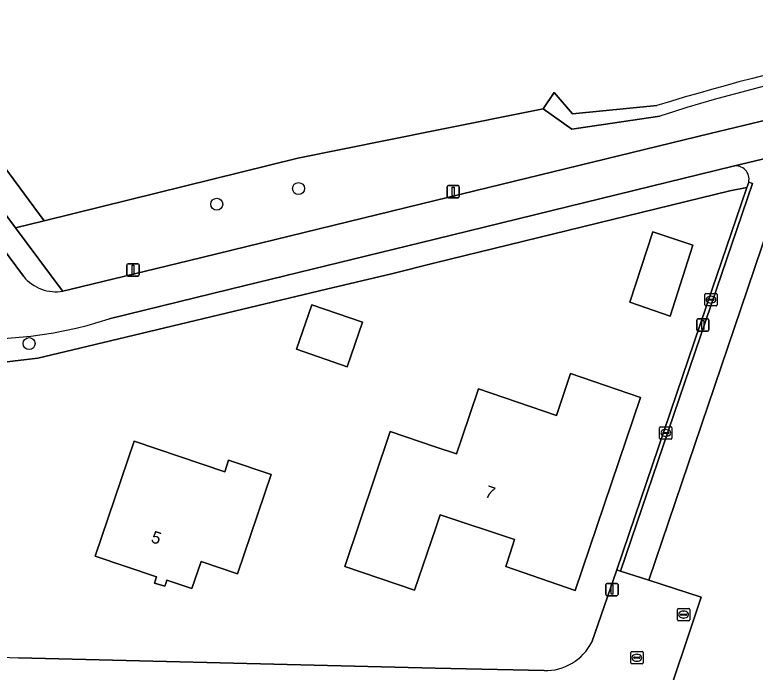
# Model space of a CAD drawing. Extents: x 163426 to 164192, y 380329 to 381641.
# Drawn here: x 163965.7 to 164026.1, y 380968.8 to 381022.4 of the extents above; entities that cross this region are included whole.
import ezdxf

# ---------------------------------------------------------------- set-up
doc = ezdxf.new("R2010")
doc.units = 0
for name, color, linetype in [('IMGEO_Boom', 7, 'Continuous'), ('IMGEO_Brandkraan', 7, 'Continuous'), ('IMGEO_Erf', 7, 'Continuous'), ('IMGEO_Fietspad_open', 7, 'Continuous'), ('IMGEO_Groenvoorziening', 7, 'Continuous'), ('IMGEO_Hek', 7, 'Continuous'), ('IMGEO_Kolk', 7, 'Continuous'), ('IMGEO_Lichtmast', 7, 'Continuous'), ('IMGEO_Pand', 7, 'Continuous'), ('IMGEO_Pand_nummerreeks', 7, 'Continuous'), ('IMGEO_Rijbaan_lokaal_open', 7, 'Continuous'), ('IMGEO_Voetpad_open', 7, 'Continuous'), ('IMGEO_Waterloop', 7, 'Continuous')]:
    doc.layers.add(name, color=color, linetype=linetype)

msp = doc.modelspace()

# ---------------------------------------------------------------- linework, layer by layer
at = {"layer": 'IMGEO_Boom'}
for centre in [(163988.865, 381008.202), (163982.196, 381006.926), (163966.911, 380995.571)]:
    msp.add_circle(centre, 0.489, dxfattribs=at)
at = {"layer": 'IMGEO_Brandkraan'}
for p, q in [((164019.731, 380973.078), (164019.731, 380973.93)), ((164019.806, 380974.004), (164020.658, 380974.004)), ((164020.219, 380973.784), (164020.244, 380973.784)), ((164020.732, 380973.93), (164020.732, 380973.078)), ((164019.99, 380973.498), (164019.99, 380973.51)), ((164020.428, 380973.461), (164020.03, 380973.461)), ((164020.033, 380973.547), (164020.431, 380973.547)), ((164020.242, 380973.224), (164020.217, 380973.224)), ((164020.474, 380973.51), (164020.474, 380973.498)), ((164020.658, 380973.004), (164019.806, 380973.004))]:
    msp.add_line(p, q, dxfattribs=at)
for points in [[(164019.731, 380973.078), (164019.731, 380973.93)], [(164019.806, 380974.004), (164020.658, 380974.004)], [(164020.732, 380973.93), (164020.732, 380973.078)], [(164020.658, 380973.004), (164019.806, 380973.004)]]:
    msp.add_lwpolyline(points, dxfattribs=at)
for centre, radius, start, end in [((164019.808, 380973.928), 0.0765, 91.55205, 178.44795), ((164019.808, 380973.928), 0.0765, 91.55205, 178.44795), ((164020.656, 380973.928), 0.0765, 1.55205, 88.44795), ((164020.656, 380973.928), 0.0765, 1.55205, 88.44795), ((164020.03, 380973.507), 0.0403, 85.87752, 175.75265), ((164020.027, 380973.497), 0.0366, 178.93798, 274.71019), ((164020.431, 380973.504), 0.043, 264.86636, 352.45326), ((164020.435, 380973.509), 0.0386, 1.73085, 96.63898), ((164019.808, 380973.08), 0.0765, 181.55205, 268.44795), ((164019.808, 380973.08), 0.0765, 181.55205, 268.44795), ((164020.656, 380973.08), 0.0765, 271.55205, 358.44795), ((164020.656, 380973.08), 0.0765, 271.55205, 358.44795)]:
    msp.add_arc(centre, radius, start, end, dxfattribs=at)
for centre, major_axis, ratio, start_param, end_param in [((164020.218, 380973.504), (-0.387, 0.002), 0.722429, 4.712389, 7.853982), ((164020.243, 380973.504), (-0.39, 0.002), 0.717154, 1.570796, 4.712389)]:
    msp.add_ellipse(centre, major_axis=major_axis, ratio=ratio, start_param=start_param, end_param=end_param, dxfattribs=at)
at = {"layer": 'IMGEO_Erf'}
for points in [[(163985.881, 381065.478), (163983.854, 381065.112), (163984.176, 381061.429), (163980.662, 381061.081), (163975.886, 381060.609), (163976.037, 381058.881), (163973.427, 381058.717), (163973.385, 381057.316), (163938.396, 381052.589), (163936.474, 381048.305), (163965.302, 381009.415), (163968.142, 381005.578), (163988.801, 381010.675), (164000, 381012.925), (164008.796, 381014.693), (164009.7, 381016.026), (164011.181, 381014.28), (164018.059, 381014.961)], [(163947.717, 380966.396), (163894.299, 380977.535), (163893.879, 380975.478), (163890.647, 380959.592), (163890.731, 380956.366), (163893.555, 380954.822), (163905.172, 380951.086), (163923.758, 380944.858), (164044.028, 380904.553), (164047.573, 380932.485), (164051.149, 380955.68), (164051.075, 380964.76), (164050.906, 381000), (164050.855, 381010.828), (164044.976, 381010.935), (164033.301, 381009.851), (164028.463, 381008.901), (164025.441, 381000), (164017.396, 380976.301), (164021.658, 380974.921), (164011.506, 380944.546), (164004.376, 380947.063), (164007.582, 380956.643)], [(164022.57, 381000), (164024.898, 381006.842), (164025.394, 381008.299), (164023.996, 381008.024), (164000, 381002.141), (163996.432, 381001.266), (163991.135, 381000), (163970.466, 380995.06), (163967.625, 380994.381), (163961.405, 380993.65), (163960.215, 380993.613), (163954.592, 380993.795), (163949.019, 380994.564), (163937.098, 380997.759), (163924.687, 381000), (163899.949, 381004.467), (163899.243, 381001.078), (163899.018, 381000), (163895.976, 380985.403), (163895.569, 380983.45), (163954.825, 380971.177)], [(164012.755, 380971.267), (164014.792, 380977.145), (164022.57, 381000)], [(163966.04, 380969.974), (164000, 380969.153), (164008.865, 380968.939)]]:
    msp.add_lwpolyline(points, dxfattribs=at)
for points in [[(164015.845, 380998.943), (164017.734, 381004.668), (164020.98, 381003.59), (164019.137, 380997.818)], [(163988.683, 380995.119), (163989.936, 380998.744), (163994.064, 380997.317), (163992.811, 380993.692)], [(164003.518, 380991.881), (164009.871, 380989.723), (164011.027, 380993.132), (164016.727, 380991.196), (164011.412, 380975.48), (164005.74, 380977.433), (164006.095, 380978.496), (164006.468, 380979.615), (164000.397, 380981.64), (164000.013, 380980.488), (163998.305, 380975.5), (163992.637, 380977.419), (163996.329, 380988.416), (164000, 380987.171), (164001.725, 380986.586), (164002.129, 380987.779)], [(163975.46, 380987.621), (163982.853, 380985.131), (163983.15, 380986.086), (163986.638, 380984.906), (163983.902, 380976.821), (163980.931, 380977.822), (163980.164, 380975.625), (163978.137, 380976.31), (163978.04, 380976.035), (163977.967, 380975.83), (163977.134, 380976.078), (163977.286, 380976.589), (163972.298, 380978.252)]]:
    msp.add_lwpolyline(points, close=True, dxfattribs=at)
for centre, radius, start, end in [((164066.317, 380859.787), 162.505, 94.22056, 107.2752), ((163968.587, 381046.594), 76.663, 259.6587, 268.09622), ((164008.953, 380973.206), 4.268, 268.81796, 332.9795)]:
    msp.add_arc(centre, radius, start, end, dxfattribs=at)
at = {"layer": 'IMGEO_Fietspad_open'}
for points in [[(163966.446, 381001.057), (163930.523, 381049.491), (163926.717, 381054.622), (163925.556, 381056.187)], [(164038.024, 381016.446), (164022.398, 381012.694), (164000, 381007.225), (163979.878, 381002.33), (163970.33, 381000), (163969.654, 380999.835)], [(163973.446, 380997.596), (163983.281, 381000), (164000, 381004.087), (164024.271, 381010.02), (164029.636, 381011.297), (164044.978, 381014.921)]]:
    msp.add_lwpolyline(points, dxfattribs=at)
for centre, radius, start, end in [((163969.159, 381003.295), 3.517, 219.52759, 249.55059), ((163969.115, 381003.289), 3.495, 250.18958, 278.87643), ((163963.36, 381028.213), 32.235, 261.55505, 288.23327)]:
    msp.add_arc(centre, radius, start, end, dxfattribs=at)
at = {"layer": 'IMGEO_Groenvoorziening'}
msp.add_lwpolyline([(163936.474, 381048.305), (163933.77, 381048.138), (163965.814, 381005.004), (163968.142, 381005.578), (163965.302, 381009.415)], close=True, dxfattribs=at)
for points in [[(164018.294, 381014.111), (164011.14, 381013.031), (164008.796, 381014.693), (164000, 381012.925), (163988.801, 381010.675), (163968.142, 381005.578), (163965.814, 381005.004), (163969.531, 381000), (163969.654, 380999.835), (163970.33, 381000), (163979.878, 381002.33), (164000, 381007.225), (164022.398, 381012.694), (164038.024, 381016.446)], [(164024.271, 381010.02), (164000, 381004.087), (163983.281, 381000), (163973.446, 380997.596)], [(163894.123, 381002.969), (163893.814, 381002.022), (163897.624, 381001.36), (163899.243, 381001.078), (163899.949, 381004.467), (163924.687, 381000), (163937.098, 380997.759), (163949.019, 380994.564), (163954.592, 380993.795), (163960.215, 380993.613), (163961.405, 380993.65), (163967.625, 380994.381), (163970.466, 380995.06), (163991.135, 381000), (163996.432, 381001.266), (164000, 381002.141), (164023.996, 381008.024), (164025.394, 381008.299), (164025.538, 381008.722)]]:
    msp.add_lwpolyline(points, dxfattribs=at)
for centre, radius, start, end in [((164063.698, 380870.896), 150.24, 93.46108, 107.59041), ((164024.49, 381008.966), 1.076, 346.88338, 101.73176), ((163963.36, 381028.213), 32.235, 261.55505, 288.23327)]:
    msp.add_arc(centre, radius, start, end, dxfattribs=at)
at = {"layer": 'IMGEO_Hek'}
msp.add_lwpolyline([(163965.814, 381005.004), (163968.142, 381005.578)], dxfattribs=at)
at = {"layer": 'IMGEO_Kolk'}
for p, q in [((164022.038, 380999.653), (164022.89, 380999.653)), ((164021.963, 380998.727), (164021.963, 380999.579)), ((164022.222, 380999.147), (164022.222, 380999.159)), ((164022.66, 380999.11), (164022.262, 380999.11)), ((164022.265, 380999.196), (164022.663, 380999.196)), ((164022.451, 380999.433), (164022.476, 380999.433)), ((164022.706, 380999.159), (164022.706, 380999.147)), ((164022.964, 380999.579), (164022.964, 380998.727)), ((164022.89, 380998.653), (164022.038, 380998.653)), ((164022.474, 380998.873), (164022.449, 380998.873)), ((164018.359, 380988.796), (164019.211, 380988.796)), ((164018.284, 380987.87), (164018.284, 380988.722)), ((164018.543, 380988.29), (164018.543, 380988.302)), ((164018.981, 380988.253), (164018.583, 380988.253)), ((164018.586, 380988.339), (164018.984, 380988.339)), ((164018.772, 380988.576), (164018.797, 380988.576)), ((164019.027, 380988.302), (164019.027, 380988.29)), ((164019.285, 380988.722), (164019.285, 380987.87)), ((164019.211, 380987.796), (164018.359, 380987.796)), ((164018.795, 380988.016), (164018.77, 380988.016)), ((164015.927, 380969.566), (164015.927, 380970.418)), ((164016.002, 380970.492), (164016.854, 380970.492)), ((164016.415, 380970.272), (164016.44, 380970.272)), ((164016.928, 380970.418), (164016.928, 380969.566)), ((164016.854, 380969.492), (164016.002, 380969.492)), ((164016.186, 380969.986), (164016.186, 380969.998)), ((164016.624, 380969.949), (164016.226, 380969.949)), ((164016.229, 380970.035), (164016.627, 380970.035)), ((164016.438, 380969.712), (164016.413, 380969.712)), ((164016.67, 380969.998), (164016.67, 380969.986))]:
    msp.add_line(p, q, dxfattribs=at)
for points in [[(164022.038, 380999.653), (164022.89, 380999.653)], [(164021.963, 380998.727), (164021.963, 380999.579)], [(164022.964, 380999.579), (164022.964, 380998.727)], [(164022.89, 380998.653), (164022.038, 380998.653)], [(164018.359, 380988.796), (164019.211, 380988.796)], [(164018.284, 380987.87), (164018.284, 380988.722)], [(164019.285, 380988.722), (164019.285, 380987.87)], [(164019.211, 380987.796), (164018.359, 380987.796)], [(164015.927, 380969.566), (164015.927, 380970.418)], [(164016.002, 380970.492), (164016.854, 380970.492)], [(164016.928, 380970.418), (164016.928, 380969.566)], [(164016.854, 380969.492), (164016.002, 380969.492)]]:
    msp.add_lwpolyline(points, dxfattribs=at)
for centre, radius, start, end in [((164022.04, 380999.577), 0.0765, 91.55205, 178.44795), ((164022.04, 380999.577), 0.0765, 91.55205, 178.44795), ((164022.888, 380999.577), 0.0765, 1.55205, 88.44795), ((164022.888, 380999.577), 0.0765, 1.55205, 88.44795), ((164022.262, 380999.156), 0.0403, 85.87752, 175.75265), ((164022.259, 380999.146), 0.0366, 178.93798, 274.71019), ((164022.663, 380999.153), 0.043, 264.86636, 352.45326), ((164022.667, 380999.158), 0.0386, 1.73085, 96.63898), ((164022.04, 380998.729), 0.0765, 181.55205, 268.44795), ((164022.04, 380998.729), 0.0765, 181.55205, 268.44795), ((164022.888, 380998.729), 0.0765, 271.55205, 358.44795), ((164022.888, 380998.729), 0.0765, 271.55205, 358.44795), ((164018.361, 380988.72), 0.0765, 91.55205, 178.44795), ((164018.361, 380988.72), 0.0765, 91.55205, 178.44795), ((164019.209, 380988.72), 0.0765, 1.55205, 88.44795), ((164019.209, 380988.72), 0.0765, 1.55205, 88.44795), ((164018.583, 380988.299), 0.0403, 85.87752, 175.75265), ((164018.58, 380988.289), 0.0366, 178.93798, 274.71019), ((164018.984, 380988.296), 0.043, 264.86636, 352.45326), ((164018.988, 380988.301), 0.0386, 1.73085, 96.63898), ((164018.361, 380987.872), 0.0765, 181.55205, 268.44795), ((164018.361, 380987.872), 0.0765, 181.55205, 268.44795), ((164019.209, 380987.872), 0.0765, 271.55205, 358.44795), ((164019.209, 380987.872), 0.0765, 271.55205, 358.44795), ((164016.004, 380970.416), 0.0765, 91.55205, 178.44795), ((164016.004, 380970.416), 0.0765, 91.55205, 178.44795), ((164016.852, 380970.416), 0.0765, 1.55205, 88.44795), ((164016.852, 380970.416), 0.0765, 1.55205, 88.44795), ((164016.004, 380969.568), 0.0765, 181.55205, 268.44795), ((164016.004, 380969.568), 0.0765, 181.55205, 268.44795), ((164016.226, 380969.995), 0.0403, 85.87752, 175.75265), ((164016.223, 380969.985), 0.0366, 178.93798, 274.71019), ((164016.627, 380969.992), 0.043, 264.86636, 352.45326), ((164016.631, 380969.997), 0.0386, 1.73085, 96.63898), ((164016.852, 380969.568), 0.0765, 271.55205, 358.44795), ((164016.852, 380969.568), 0.0765, 271.55205, 358.44795)]:
    msp.add_arc(centre, radius, start, end, dxfattribs=at)
for centre, major_axis, ratio, start_param, end_param in [((164022.45, 380999.153), (-0.387, 0.002), 0.722429, 4.712389, 7.853982), ((164022.475, 380999.153), (-0.39, 0.002), 0.717154, 1.570796, 4.712389), ((164018.771, 380988.296), (-0.387, 0.002), 0.722429, 4.712389, 7.853982), ((164018.796, 380988.296), (-0.39, 0.002), 0.717154, 1.570796, 4.712389), ((164016.414, 380969.992), (-0.387, 0.002), 0.722429, 4.712389, 7.853982), ((164016.439, 380969.992), (-0.39, 0.002), 0.717154, 1.570796, 4.712389)]:
    msp.add_ellipse(centre, major_axis=major_axis, ratio=ratio, start_param=start_param, end_param=end_param, dxfattribs=at)
at = {"layer": 'IMGEO_Lichtmast'}
for p, q in [((164000.968, 381007.544), (164000.968, 381008.344)), ((164000.968, 381008.344), (164000.968, 381007.544)), ((164001.068, 381008.444), (164001.858, 381008.444)), ((164001.858, 381008.444), (164001.068, 381008.444)), ((164001.958, 381008.344), (164001.958, 381007.544)), ((164001.958, 381007.544), (164001.958, 381008.344)), ((164001.858, 381007.444), (164001.068, 381007.444)), ((164001.068, 381007.444), (164001.858, 381007.444)), ((163974.981, 381002.081), (163975.771, 381002.081)), ((163975.771, 381002.081), (163974.981, 381002.081)), ((163974.881, 381001.181), (163974.881, 381001.981)), ((163974.881, 381001.981), (163974.881, 381001.181)), ((163975.871, 381001.981), (163975.871, 381001.181)), ((163975.871, 381001.181), (163975.871, 381001.981)), ((163975.771, 381001.081), (163974.981, 381001.081)), ((163974.981, 381001.081), (163975.771, 381001.081)), ((164021.302, 380996.688), (164021.302, 380997.488)), ((164021.302, 380997.488), (164021.302, 380996.688)), ((164021.402, 380997.588), (164022.192, 380997.588)), ((164022.192, 380997.588), (164021.402, 380997.588)), ((164022.292, 380997.488), (164022.292, 380996.688)), ((164022.292, 380996.688), (164022.292, 380997.488)), ((164022.192, 380996.588), (164021.402, 380996.588)), ((164021.402, 380996.588), (164022.192, 380996.588)), ((164013.902, 380975.145), (164013.902, 380975.945)), ((164013.902, 380975.945), (164013.902, 380975.145)), ((164014.002, 380976.045), (164014.792, 380976.045)), ((164014.792, 380976.045), (164014.002, 380976.045)), ((164014.892, 380975.945), (164014.892, 380975.145)), ((164014.892, 380975.145), (164014.892, 380975.945)), ((164014.792, 380975.045), (164014.002, 380975.045)), ((164014.002, 380975.045), (164014.792, 380975.045))]:
    msp.add_line(p, q, dxfattribs=at)
for points in [[(164001.388, 381008.319), (164001.538, 381008.319), (164001.538, 381007.569), (164001.388, 381007.569), (164001.388, 381008.319)], [(163975.301, 381001.956), (163975.451, 381001.956), (163975.451, 381001.206), (163975.301, 381001.206), (163975.301, 381001.956)], [(164021.722, 380997.463), (164021.872, 380997.463), (164021.872, 380996.713), (164021.722, 380996.713), (164021.722, 380997.463)], [(164014.322, 380975.92), (164014.472, 380975.92), (164014.472, 380975.17), (164014.322, 380975.17), (164014.322, 380975.92)]]:
    msp.add_lwpolyline(points, dxfattribs=at)
for centre, start, end in [((164001.068, 381008.344), 90, 180), ((164001.068, 381008.344), 90, 180), ((164001.858, 381008.344), 0, 90), ((164001.858, 381008.344), 360, 90), ((164001.068, 381007.544), 180, 270), ((164001.068, 381007.544), 180, 270), ((164001.858, 381007.544), 270, 0), ((164001.858, 381007.544), 270, 0), ((163974.981, 381001.981), 90, 180), ((163974.981, 381001.981), 90, 180), ((163975.771, 381001.981), 0, 90), ((163975.771, 381001.981), 360, 90), ((163974.981, 381001.181), 180, 270), ((163974.981, 381001.181), 180, 270), ((163975.771, 381001.181), 270, 0), ((163975.771, 381001.181), 270, 0), ((164021.402, 380997.488), 90, 180), ((164021.402, 380997.488), 90, 180), ((164022.192, 380997.488), 0, 90), ((164022.192, 380997.488), 360, 90), ((164021.402, 380996.688), 180, 270), ((164021.402, 380996.688), 180, 270), ((164022.192, 380996.688), 270, 0), ((164022.192, 380996.688), 270, 0), ((164014.002, 380975.945), 90, 180), ((164014.002, 380975.945), 90, 180), ((164014.792, 380975.945), 0, 90), ((164014.792, 380975.945), 360, 90), ((164014.002, 380975.145), 180, 270), ((164014.002, 380975.145), 180, 270), ((164014.792, 380975.145), 270, 0), ((164014.792, 380975.145), 270, 0)]:
    msp.add_arc(centre, 0.1, start, end, dxfattribs=at)
at = {"layer": 'IMGEO_Pand'}
for points in [[(164015.845, 380998.943), (164019.137, 380997.818), (164020.98, 381003.59), (164017.734, 381004.668)], [(163988.683, 380995.119), (163992.811, 380993.692), (163994.064, 380997.317), (163989.936, 380998.744)], [(164016.727, 380991.196), (164011.027, 380993.132), (164009.871, 380989.723), (164003.518, 380991.881), (164002.129, 380987.779), (164001.725, 380986.586), (164000, 380987.171), (163996.329, 380988.416), (163992.637, 380977.419), (163998.305, 380975.5), (164000.013, 380980.488), (164000.397, 380981.64), (164006.468, 380979.615), (164006.095, 380978.496), (164005.74, 380977.433), (164011.412, 380975.48)], [(163978.04, 380976.035), (163978.137, 380976.31), (163980.164, 380975.625), (163980.931, 380977.822), (163983.902, 380976.821), (163986.638, 380984.906), (163983.15, 380986.086), (163982.853, 380985.131), (163975.46, 380987.621), (163972.298, 380978.252), (163977.286, 380976.589), (163977.134, 380976.078), (163977.967, 380975.83)]]:
    msp.add_lwpolyline(points, close=True, dxfattribs=at)
at = {"layer": 'IMGEO_Rijbaan_lokaal_open'}
msp.add_lwpolyline([(164014.792, 380977.145), (164015.09, 380977.048), (164022.906, 381000), (164025.84, 381008.617), (164025.538, 381008.722), (164025.394, 381008.299), (164024.898, 381006.842), (164022.57, 381000)], close=True, dxfattribs=at)
for points in [[(164007.582, 380956.643), (164004.376, 380947.063), (164011.506, 380944.546), (164021.658, 380974.921), (164017.396, 380976.301), (164015.09, 380977.048), (164014.792, 380977.145), (164012.755, 380971.267)], [(164008.865, 380968.939), (164000, 380969.153), (163966.04, 380969.974)]]:
    msp.add_lwpolyline(points, dxfattribs=at)
for centre, radius, start, end in [((163968.587, 381046.594), 76.663, 259.6587, 268.09622), ((164008.953, 380973.206), 4.268, 268.81796, 332.9795)]:
    msp.add_arc(centre, radius, start, end, dxfattribs=at)
at = {"layer": 'IMGEO_Voetpad_open'}
for points in [[(163930.805, 381056.087), (163925.556, 381056.187), (163926.717, 381054.622), (163930.523, 381049.491), (163966.446, 381001.057)], [(163969.654, 380999.835), (163969.531, 381000), (163965.814, 381005.004), (163933.77, 381048.138)], [(164029.636, 381011.297), (164024.271, 381010.02)], [(164025.538, 381008.722), (164025.84, 381008.617), (164022.906, 381000), (164015.09, 380977.048), (164017.396, 380976.301), (164025.441, 381000), (164028.463, 381008.901), (164029.093, 381010.758)]]:
    msp.add_lwpolyline(points, dxfattribs=at)
for centre, radius, start, end in [((164024.49, 381008.966), 1.076, 346.88338, 101.73176), ((163969.159, 381003.295), 3.517, 219.52759, 249.55059), ((163969.115, 381003.289), 3.495, 250.18958, 278.87643)]:
    msp.add_arc(centre, radius, start, end, dxfattribs=at)
at = {"layer": 'IMGEO_Waterloop'}
msp.add_lwpolyline([(164018.059, 381014.961), (164011.181, 381014.28), (164009.7, 381016.026), (164008.796, 381014.693), (164011.14, 381013.031), (164018.294, 381014.111)], dxfattribs=at)
for centre, radius, start, end in [((164066.317, 380859.787), 162.505, 94.22056, 107.2752), ((164063.698, 380870.896), 150.24, 93.46108, 107.59041)]:
    msp.add_arc(centre, radius, start, end, dxfattribs=at)

# ---------------------------------------------------------------- texts
at = {"layer": 'IMGEO_Pand_nummerreeks'}
for s, rotation, p in [('7', 341.55649, (164003.969, 380983.105)), ('5', 341.53228, (163976.769, 380979.416))]:
    msp.add_text(s, height=1, rotation=rotation, dxfattribs=at).set_placement(p)

doc.saveas('drawing.dxf')
